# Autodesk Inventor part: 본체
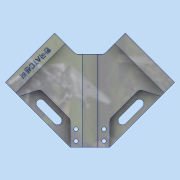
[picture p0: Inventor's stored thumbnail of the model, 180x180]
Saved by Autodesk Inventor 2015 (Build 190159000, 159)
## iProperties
Created: 2019-04
Part Number: 본체
Material: 알루미늄 6061
Document SubType Name: Modeling
Designer: SCD-A02
Density: 2.7 g/cm^3
Appearance: 알루미늄 - 평지
Author: SCD-A02
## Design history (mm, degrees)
sketch "스케치1"
  geometry: L1 (-84.853, 0)-(0, 84.853); L2 (0, 84.853)-(84.853, 0); L3 (84.853, 0)-(0, -84.853); L4 (0, -84.853)-(-84.853, 0); L5 (-84.853, 0)-(84.853, 0); L6 (0, 84.853)-(0, -84.853); 1 further point
  constraints: 12 end point, 2 midpoint, 2 parallel, 1 perpendicular
extrude "돌출1" new body sketch "스케치1" distance "d2" = 18; taper "d3" = 0 deg
sketch "스케치2"
  geometry: L1 (0, 84.853)-(-84.853, 0) reference; L2 (-84.853, 0)-(0, -84.853) reference; L3 (0, -84.853)-(84.853, 0) reference; L4 (84.853, 0)-(0, 84.853) reference; L5 (-84.853, 0)-(-50.467, -34.386); L6 (-84.853, 0)-(-49.497, 35.355); L7 (64.853, 0)-(64.853, 20); L8 (64.853, 0)-(64.853, -20); L9 (64.853, -20)-(84.853, 0); L10 (84.853, 0)-(64.853, 20); 1 further point
  constraints: 12 end point, 5 point on line, 1 collinear, 1 vertical
  dimensions: "d6" = 20 distance of L3.end L7.start; "d7" = 20 distance from line of L3.end L8; "d8" = 70 distance from line of L6.end L4; "d9" = 48.62899 distance from line of L5.end L1
extrude "돌출2" cut sketch "스케치2" distance "d10" = 18; taper "d11" = 0 deg
sketch "스케치3"
  geometry: L1 (64.853, -20)-(64.853, 20) reference; L2 (64.853, 20)-(0, 84.853) reference; L3 (0, -84.853)-(64.853, -20) reference; L4 (64.853, 0)-(-28.147, 0); L5 (-84.853, 0)-(-49.497, -35.355); L6 (-84.853, 0)-(-49.497, 35.355); L7 (-49.497, -35.355)-(-28.147, -14.005); L8 (-49.497, 35.355)-(-28.147, 14.005); L9 (-28.147, 0)-(-28.147, 5.408); L10 (-28.147, 5.408)-(-28.147, 14.005); L11 (-28.147, 0)-(-28.147, -14.005); 1 further point
  constraints: 16 end point, 5 parallel, 1 horizontal, 1 midpoint, 1 point on line, 1 vertical
  dimensions: "d12" = 93 distance of L4.start L4.end; "d13" = 50 distance of L5.start L5.end; "d14" = 50 distance of L5.start L6.end; "d15" = 76.07918 distance from line of L9.end L2
extrude "돌출3" cut sketch "스케치3" stored distance "d16" = 0; taper "d17" = 0 deg
sketch "스케치4"
  geometry: L1 (-28.147, 14.005)-(-28.147, -14.005) reference; L2 (64.853, -20)-(64.853, 20) reference; L3 (-28.147, 0)-(64.853, 0); L4 (-28.147, -8)-(64.853, -8); L5 (-28.147, 8)-(64.853, 8); L6 (-28.147, -8)-(-28.147, 8); L7 (64.853, -8)-(64.853, 8); 1 further point
  constraints: 10 end point, 2 midpoint, 2 parallel, 1 collinear, 1 perpendicular, 1 point on line
  dimensions: "d18" = 8 distance between parallel lines of L3 L4; "d19" = 8 distance between parallel lines of L3 L5
extrude "돌출4" cut sketch "스케치4" distance "d20" = 3.5; taper "d21" = 0 deg
sketch "스케치5"
  geometry: L1 (-64.853, 20)-(-64.853, -20) reference; L2 (28.147, -14.005)-(28.147, 14.005) reference; L3 (-64.853, 8)-(-64.853, -8) reference; L4 (28.147, 8)-(-64.853, 8) reference; L5 (28.147, -8)-(28.147, 8) reference; L6 (-64.853, -8)-(28.147, -8) reference; L7 (-64.853, 0)-(28.147, 0); L8 (-64.853, 6)-(28.147, 6); L9 (-64.853, -6)-(28.147, -6); L10 (-64.853, -6)-(-64.853, 6); L11 (28.147, -6)-(28.147, 6); 1 further point
  constraints: 10 end point, 2 collinear, 2 midpoint, 2 parallel
  dimensions: "d22" = 6 distance between parallel lines of L7 L8; "d23" = 6 distance between parallel lines of L7 L9
extrude "돌출5" cut sketch "스케치5" distance "d24" = 3; taper "d25" = 0 deg
sketch "스케치6"
  geometry: L1 (-49.497, -35.355)-(0, -84.853) reference; L2 (0, -84.853)-(64.853, -20) reference; L3 (-28.147, -14.005)-(-28.147, -8) reference; L4 (-28.147, -8)-(64.853, -8) reference; L5 (64.853, -8)-(64.853, -20) reference; L6 (64.853, -20)-(0, -84.853) reference; L7 (0, -84.853)-(-49.497, -35.355) reference; L8 (-49.497, -35.355)-(-28.147, -14.005) reference; L9 (-28.147, 8)-(-28.147, 14.005) reference; L10 (-28.147, 14.005)-(-49.497, 35.355) reference; L11 (-49.497, 35.355)-(0, 84.853) reference; L12 (0, 84.853)-(64.853, 20) reference; L13 (64.853, 20)-(64.853, 8) reference; L14 (64.853, 8)-(-28.147, 8) reference; L15 (-38.891, -24.749)-(10.607, -74.246); L16 (0, -84.853)-(10.607, -74.246); L17 (-49.497, -35.355)-(-38.891, -24.749); 1 further point
  constraints: 6 end point, 2 collinear, 1 parallel
  dimensions: "d26" = 15 distance between parallel lines of L1 L15
extrude "돌출6" join sketch "스케치6" distance "d27" = 24; taper "d28" = 0 deg
sketch "스케치7"
  geometry: L1 (0, 84.853)-(-49.497, 35.355) reference; L2 (-28.147, -14.005)-(-28.147, -8) reference; L3 (-28.147, -8)-(64.853, -8) reference; L4 (64.853, -8)-(64.853, -20) reference; L5 (64.853, -20)-(10.607, -74.246) reference; L6 (-38.891, -24.749)-(10.607, -74.246) reference; L7 (-49.497, -35.355)-(-38.891, -24.749) reference; L8 (0, -84.853)-(-49.497, -35.355) reference; L9 (10.607, -74.246)-(0, -84.853) reference; L10 (-38.891, -24.749)-(-28.147, -14.005) reference; L11 (-28.147, 8)-(-28.147, 14.005) reference; L12 (-28.147, 14.005)-(-49.497, 35.355) reference; L13 (-49.497, 35.355)-(0, 84.853) reference; L14 (0, 84.853)-(64.853, 20) reference; L15 (64.853, 20)-(64.853, 8) reference; L16 (64.853, 8)-(-28.147, 8) reference; L17 (10.607, 74.246)-(-38.891, 24.749); L18 (-38.891, 24.749)-(-49.497, 35.355); L19 (10.607, 74.246)-(0, 84.853); 1 further point
  constraints: 6 end point, 2 collinear, 1 parallel
  dimensions: "d29" = 15 distance between parallel lines of L1 L17
extrude "돌출7" join sketch "스케치7" distance "d30" = 24; taper "d31" = 0 deg
sketch "스케치8"
  geometry: L1 (10.607, -74.246)-(64.853, -20) reference; L2 (-28.147, -14.005)-(-28.147, -8) reference; L3 (-28.147, -8)-(64.853, -8) reference; L4 (64.853, -8)-(64.853, -20) reference; L5 (64.853, -20)-(10.607, -74.246) reference; L6 (-38.891, -24.749)-(10.607, -74.246) reference; L7 (-49.497, -35.355)-(-38.891, -24.749) reference; L8 (0, -84.853)-(-49.497, -35.355) reference; L9 (10.607, -74.246)-(0, -84.853) reference; L10 (-38.891, -24.749)-(-28.147, -14.005) reference; L11 (-28.147, 8)-(-28.147, 14.005) reference; L12 (-28.147, 14.005)-(-38.891, 24.749) reference; L13 (10.607, 74.246)-(-38.891, 24.749) reference; L14 (0, 84.853)-(10.607, 74.246) reference; L15 (-49.497, 35.355)-(0, 84.853) reference; L16 (-38.891, 24.749)-(-49.497, 35.355) reference; L17 (64.853, 8)-(-28.147, 8) reference; L18 (64.853, 20)-(64.853, 8) reference; L19 (10.607, 74.246)-(64.853, 20) reference; L20 (-28.147, -14.005)-(-28.147, -8) reference; L21 (-28.147, -8)-(64.853, -8) reference; L22 (64.853, -8)-(64.853, -20) reference; L23 (64.853, -20)-(10.607, -74.246) reference; L24 (-38.891, -24.749)-(10.607, -74.246) reference; L25 (-49.497, -35.355)-(-38.891, -24.749) reference; L26 (0, -84.853)-(-49.497, -35.355) reference; L27 (10.607, -74.246)-(0, -84.853) reference; L28 (-38.891, -24.749)-(-28.147, -14.005) reference; L29 (-28.147, 8)-(-28.147, 14.005) reference; L30 (-28.147, 14.005)-(-38.891, 24.749) reference; L31 (10.607, 74.246)-(-38.891, 24.749) reference; L32 (0, 84.853)-(10.607, 74.246) reference; L33 (-49.497, 35.355)-(0, 84.853) reference; L34 (-38.891, 24.749)-(-49.497, 35.355) reference; L35 (64.853, 8)-(-28.147, 8) reference; L36 (64.853, 20)-(64.853, 8) reference; L37 (10.607, 74.246)-(64.853, 20) reference; L38 (-28.147, -14.005)-(-28.147, -8) reference; L39 (-28.147, -8)-(64.853, -8) reference; L40 (64.853, -8)-(64.853, -20) reference; L41 (64.853, -20)-(10.607, -74.246) reference; L42 (-38.891, -24.749)-(10.607, -74.246) reference; L43 (-49.497, -35.355)-(-38.891, -24.749) reference; L44 (0, -84.853)-(-49.497, -35.355) reference; L45 (10.607, -74.246)-(0, -84.853) reference; L46 (-38.891, -24.749)-(-28.147, -14.005) reference; L47 (-28.147, 8)-(-28.147, 14.005) reference; L48 (-28.147, 14.005)-(-38.891, 24.749) reference; L49 (10.607, 74.246)-(-38.891, 24.749) reference; L50 (0, 84.853)-(10.607, 74.246) reference; L51 (-49.497, 35.355)-(0, 84.853) reference; L52 (-38.891, 24.749)-(-49.497, 35.355) reference; L53 (64.853, 8)-(-28.147, 8) reference; L54 (64.853, 20)-(64.853, 8) reference; L55 (10.607, 74.246)-(64.853, 20) reference; L56 (64.853, 0)-(23.588, 0); L57 (64.853, -20)-(36.569, -20); L58 (14.142, -70.711)-(7.071, -49.497); L59 (-28.147, -14.005)-(-28.147, -8) reference; L60 (-28.147, -8)-(64.853, -8) reference; L61 (64.853, -8)-(64.853, -20) reference; L62 (64.853, -20)-(10.607, -74.246) reference; L63 (-38.891, -24.749)-(10.607, -74.246) reference; L64 (-49.497, -35.355)-(-38.891, -24.749) reference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; 1 further point
  constraints: 14 end point, 3 parallel, 3 point on line, 1 collinear, 1 horizontal
  dimensions: "d35" = 20 distance between parallel lines of L56 L57; "d57" = 18.4349 deg angle of L18 L58; "d58" = 8 distance between parallel lines of L17 L56; "d59" = 20 distance between parallel lines of L5 L77; "d60" = 80 distance between parallel lines of L14 L78; "d61" = 76.79361 distance from line of L18.start L58; "d62" = 14.14214 distance from line of L56.start L79; "d63" = 43.32107 distance from line of L56.end L79; "d64" = 100 distance from line of L58.start L79; "d65" = 86.06602 distance from line of L78.start L36
extrude "돌출10" cut sketch "스케치8" distance "d68" = 10; taper "d69" = 0 deg
sketch "스케치9"
  geometry: L1 (64.853, -20)-(14.142, -70.711) reference; L2 (-28.147, -14.005)-(-28.147, 14.005) reference; L3 (-28.147, 14.005)-(-49.497, 35.355) reference; L4 (-49.497, 35.355)-(0, 84.853) reference; L5 (0, 84.853)-(64.853, 20) reference; L6 (64.853, 20)-(64.853, -20) reference; L7 (64.853, -20)-(14.142, -70.711) reference; L8 (14.142, -70.711)-(0, -84.853) reference; L9 (0, -84.853)-(-49.497, -35.355) reference; L10 (-49.497, -35.355)-(-28.147, -14.005) reference; L11 (64.853, -20)-(36.569, -20) reference; L12 (36.569, -20)-(7.071, -49.497) reference; L13 (7.071, -49.497)-(14.142, -70.711) reference; L14 (24.395, -52.679)-(41.366, -35.709); L15 (18.031, -46.315)-(35.002, -29.345); A1 r 4.5 centre (21.213, -49.497) between (18.031, -46.315) and (24.395, -52.679); A2 r 4.5 centre (38.184, -32.527) between (41.366, -35.709) and (35.002, -29.345); 1 further point
  constraints: 4 end point, 4 point on circle, 4 tangent, 2 centre point, 2 parallel
  dimensions: "d75" = 4.5 radius of A2; "d76" = 5.5 distance between parallel lines of L1 L14; "d77" = 23.48707 distance from line of L14.end L6; "d78" = 40.45763 distance from line of L14.start L6
extrude "돌출11" cut sketch "스케치9" stored distance "d79" = 10; taper "d80" = 0 deg
sketch "스케치10"
  geometry: L1 (64.853, -20)-(64.853, -8) reference; L2 (64.853, 0)-(27.579, 0); L3 (64.853, -14)-(27.579, -14); L4 (-28.147, -14.005)-(-28.147, -8) reference; L5 (-28.147, -8)-(64.853, -8) reference; L6 (64.853, -8)-(64.853, -20) reference; L7 (64.853, -20)-(36.569, -20) reference; L8 (36.569, -20)-(7.071, -49.497) reference; L9 (7.071, -49.497)-(14.142, -70.711) reference; L10 (14.142, -70.711)-(10.607, -74.246) reference; L11 (10.607, -74.246)-(0, -84.853) reference; L12 (0, -84.853)-(-49.497, -35.355) reference; L13 (-49.497, -35.355)-(-38.891, -24.749) reference; L14 (-38.891, -24.749)-(-28.147, -14.005) reference; L15 (-38.891, -24.749)-(10.607, -74.246) reference; L16 (-28.147, 8)-(-28.147, 14.005) reference; L17 (-28.147, 14.005)-(-38.891, 24.749) reference; L18 (10.607, 74.246)-(-38.891, 24.749) reference; L19 (0, 84.853)-(10.607, 74.246) reference; L20 (-49.497, 35.355)-(0, 84.853) reference; L21 (-38.891, 24.749)-(-49.497, 35.355) reference; L22 (64.853, 8)-(-28.147, 8) reference; L23 (64.853, 20)-(64.853, 8) reference; L24 (10.607, 74.246)-(64.853, 20) reference; L25 (58.853, -20)-(58.853, -8); L26 (46.853, -20)-(46.853, -8); 3 further points
  constraints: 8 end point, 3 parallel, 2 midpoint, 1 horizontal
  dimensions: "d81" = 14 distance between parallel lines of L2 L3; "d82" = 6 distance between parallel lines of L1 L25; "d83" = 12 distance between parallel lines of L25 L26
hole "구멍1" sketch "스케치10" at (46.853, -14), (58.853, -14) diameter "d84" = 4.5; stored, may be unused: countersink angle "d88" = 90 deg, drill point angle "d90" = 0 deg; dims "d85" = 6, "d86" = 4, "d87" = 2, "d89" = 8
sketch "스케치11"
  geometry: L1 (-18.031, -46.315)-(-35.002, -29.345) reference; L2 (-41.366, -35.709)-(-24.395, -52.679) reference; L3 (-64.853, -6)-(28.147, -6) reference; L4 (28.147, -6)-(28.147, -14.005) reference; L5 (28.147, -14.005)-(49.497, -35.355) reference; L6 (49.497, -35.355)-(0, -84.853) reference; L7 (0, -84.853)-(-64.853, -20) reference; L8 (-64.853, -20)-(-64.853, -6) reference; L9 (28.147, 6)-(-64.853, 6) reference; L10 (-64.853, 6)-(-64.853, 20) reference; L11 (-64.853, 20)-(0, 84.853) reference; L12 (0, 84.853)-(49.497, 35.355) reference; L13 (49.497, 35.355)-(28.147, 14.005) reference; L14 (28.147, 14.005)-(28.147, 6) reference; C1 r 2.25 at (-46.853, -14) reference; C2 r 2.25 at (-46.853, -14) reference; C3 r 2.25 at (-46.853, -14) reference; C4 r 2.25 at (-58.853, -14) reference; C5 r 2.25 at (-58.853, -14) reference; A1 r 4.5 centre (-38.184, -32.527) between (-35.002, -29.345) and (-41.366, -35.709) reference; A2 r 4.5 centre (-21.213, -49.497) between (-24.395, -52.679) and (-18.031, -46.315) reference; 3 further points
  constraints: 2 coincident
hole "구멍2" sketch "스케치11" at (-58.853, -14), (-46.853, -14) diameter "d91" = 8; stored, may be unused: countersink angle "d95" = 90 deg, drill point angle "d97" = 0 deg; dims "d92" = 6, "d93" = 4, "d94" = 2, "d96" = 10
fillet "모깎기1" dims "d98" = 5
fillet "모깎기3" dims "d100" = 5
fillet "모깎기4" dims "d101" = 5
sketch "스케치12"
  geometry: L1 (-49.497, -35.355)-(0, -84.853) reference; L2 (-38.891, -24.749)-(-49.497, -35.355) reference; 2 further points
  constraints: 1 other
  dimensions: "d102" = 35 distance from line of point (-19.445, -54.801) L2; "d103" = 7.5 distance from line of L1 point (-19.445, -54.801)
feature "엠보싱1" sketch "스케치12" dims "d104" = 0.5, "d105" = 0
node "솔리드1"
mirror "대칭1"
node "투영된 루프1"
node "투영된 루프2"
node "투영된 루프3"
node "절단 모서리 투영1"
node "절단 모서리 투영2"
node "절단 모서리 투영3"
node "절단 모서리 투영4"
node "절단 모서리 투영5"
node "절단 모서리 투영6"
node "절단 모서리 투영7"
node "절단 모서리 투영8"
node "절단 모서리 투영9"
